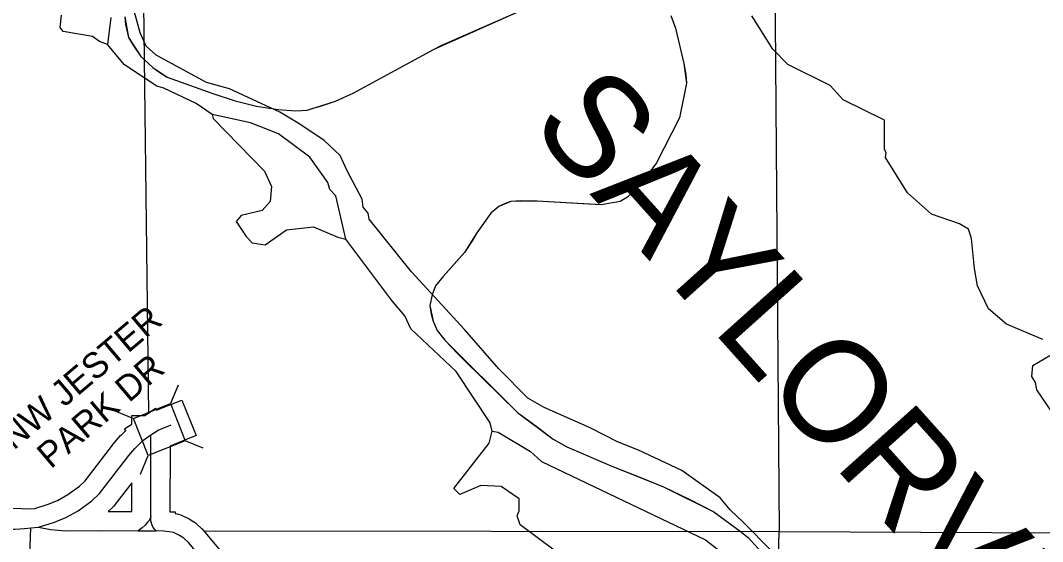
# Model space of a CAD drawing. Extents: x -1403959 to 81668, y -1400582 to 11018.
# Drawn here: x 6398.9 to 6553.7, y 9508.2 to 9587.1 of the extents above; entities that cross this region are included whole.
import ezdxf

# ---------------------------------------------------------------- set-up
doc = ezdxf.new("R2010")
doc.units = 0
for name, color, linetype in [('tdCiCoBndryTxt', 7, 'Continuous'), ('tdCiRROwnerTxt', 7, 'Continuous'), ('tdCiSecText', 7, 'Continuous'), ('tdCiSectLine', 7, 'Continuous'), ('tdCoCityStreetMajor', 7, 'Continuous'), ('tdCoClipBndry', 7, 'Continuous'), ('tdCoSectNmbr', 7, 'Continuous'), ('tdCoSurfBitum', 7, 'Continuous'), ('tdCoSurfConc', 7, 'Continuous'), ('tdCoTwpNameTxt', 7, 'Continuous')]:
    doc.layers.add(name, color=color, linetype=linetype)

msp = doc.modelspace()

# ---------------------------------------------------------------- linework, layer by layer
at = {"layer": 'tdCiCoBndryTxt'}
for points in [[(6418.65, 9524.35), (6419.75, 9525.04), (6421.71, 9525.83)], [(6401.63, 9510.33), (6404.04, 9511.09), (6405.77, 9511.8), (6407.6, 9512.84), (6409.68, 9514.34), (6410.83, 9515.43), (6415.27, 9521.22), (6416.21, 9522.26), (6417.44, 9523.49), (6418.65, 9524.35)], [(6419.42, 9509.79), (6419.19, 9510.04), (6418.99, 9510.32), (6418.83, 9510.63), (6418.72, 9510.95), (6418.65, 9511.29), (6418.63, 9511.63), (6418.63, 9511.95), (6418.65, 9524.35)], [(6418.63, 9511.95), (6418.44, 9511.42), (6418.14, 9511.08), (6417.77, 9510.63), (6417.32, 9510.23), (6416.72, 9509.8)], [(6370, 9510), (6387.18, 9510.05), (6398.08, 9510.05), (6399.48, 9510.15), (6400.45, 9510.23), (6401.63, 9510.33)], [(6401.63, 9510.33), (6403.41, 9510), (6405.77, 9509.79), (6410.89, 9509.82), (6416.72, 9509.8), (6418.29, 9509.79), (6419.42, 9509.79)], [(6441.88, 9466.82), (6441.56, 9467.69), (6441.46, 9468.69), (6441.48, 9470.01), (6441.61, 9473.37), (6441.7, 9476.58), (6441.36, 9478.55), (6439.76, 9483.71), (6437.47, 9491.1), (6436.67, 9492.76), (6435.76, 9494.12), (6434.5, 9495.86), (6424.33, 9508.02), (6423.62, 9508.68), (6422.96, 9509.1), (6422.04, 9509.52), (6421.39, 9509.64), (6420.54, 9509.76), (6419.42, 9509.79)]]:
    msp.add_lwpolyline(points, dxfattribs=at)
at = {"layer": 'tdCiRROwnerTxt'}
msp.add_lwpolyline([(6405.79, 9491.03), (6404.68, 9492.17), (6403.18, 9493.73), (6401.54, 9496.26), (6400.73, 9498.55), (6400.29, 9500.37), (6400.14, 9502.07), (6400.45, 9510.23)], dxfattribs=at)
at = {"layer": 'tdCiSecText'}
for points in [[(6422.77, 9531.84), (6421.59, 9529.06), (6423.85, 9523.45)], [(6413.19, 9527.98), (6415.98, 9526.8), (6421.59, 9529.06)], [(6417.05, 9518.4), (6418.24, 9521.18), (6415.98, 9526.8)], [(6426.57, 9522.29), (6423.85, 9523.45), (6418.24, 9521.18)]]:
    msp.add_lwpolyline(points, dxfattribs=at)
at = {"layer": 'tdCiSectLine'}
for points in [[(6397.66, 9513.24), (6400.38, 9513.14), (6401.07, 9513.19), (6403.05, 9513.82), (6404.49, 9514.41), (6406.03, 9515.29), (6407.82, 9516.58), (6408.67, 9517.38), (6412.97, 9522.99), (6413.09, 9523.14), (6413.12, 9523.17), (6414.05, 9524.21), (6414.16, 9524.32), (6414.16, 9524.32), (6414.82, 9524.98), (6414.64, 9525.25), (6415.75, 9525.95), (6415.75, 9527.25), (6417.72, 9527.25), (6419.34, 9528.39), (6419.55, 9528.09), (6420.62, 9528.52), (6423.31, 9529.61), (6425.48, 9524.22), (6422.79, 9523.14), (6421.55, 9522.64), (6421.53, 9512.69), (6422.33, 9512.68), (6422.33, 9512.42), (6422.6, 9512.36), (6422.6, 9512.36), (6422.79, 9512.32), (6422.97, 9512.26), (6423.15, 9512.2), (6423.22, 9512.16), (6424.14, 9511.75), (6424.24, 9511.71), (6424.41, 9511.62), (6424.53, 9511.54), (6425.19, 9511.12), (6425.23, 9511.09), (6425.38, 9510.98), (6425.53, 9510.86), (6425.58, 9510.81), (6426.3, 9510.15), (6426.39, 9510.07), (6426.52, 9509.93), (6426.56, 9509.88), (6436.72, 9497.72)], [(6415.73, 9512.7), (6415.73, 9517.06), (6413.13, 9513.67), (6413.01, 9513.52), (6412.88, 9513.38), (6412.83, 9513.33), (6412.18, 9512.72), (6415.73, 9512.7)]]:
    msp.add_lwpolyline(points, dxfattribs=at)
at = {"layer": 'tdCoCityStreetMajor'}
for points in [[(6417.33, 9606.13), (6418.27, 9527.53)], [(6513.07, 9606.38), (6513.8, 9509.68)], [(6426.6, 9509.78), (6513.8, 9509.68)], [(6511.21, 9405.21), (6513.8, 9509.68)], [(6513.8, 9509.68), (6610.4, 9509.24)]]:
    msp.add_lwpolyline(points, dxfattribs=at)
at = {"layer": 'tdCoClipBndry'}
for points in [[(6414.69, 9587.68), (6415.25, 9584.52), (6417.1, 9581.64), (6418.95, 9579.98), (6421.1, 9578.53), (6428.04, 9576.03), (6431.39, 9574.94), (6434.65, 9574.11), (6437.9, 9573.61), (6440.57, 9573.4), (6442.29, 9573.54), (6446.62, 9574.86), (6449.29, 9576.09), (6461.53, 9582.78), (6474.48, 9588.52)], [(6497.42, 9587.87), (6498.1, 9585.96), (6499.38, 9580.59), (6499.76, 9577.62), (6498.74, 9572.35), (6495.25, 9565.52), (6492.78, 9562.16), (6490.86, 9560.34), (6489.72, 9559.69), (6486.86, 9559.16), (6477.13, 9559.75), (6473.15, 9559.66), (6471.35, 9558.91), (6470.13, 9557.89), (6467.99, 9554.94), (6466.14, 9551.94), (6462.9, 9548.34), (6461.75, 9546.91), (6461.23, 9545.56), (6460.89, 9543.91), (6461.42, 9541.56), (6462.03, 9540.16), (6463.16, 9538.69), (6474.2, 9527.71), (6479.59, 9523.68), (6481.67, 9522.52), (6488.45, 9519.58), (6496.3, 9516.44), (6503.92, 9512.68), (6508.11, 9509.57), (6509.16, 9508.71), (6514.03, 9503.4)]]:
    msp.add_lwpolyline(points, dxfattribs=at)
at = {"layer": 'tdCoSurfBitum'}
for points in [[(6512.78, 9506.67), (6508.36, 9511.11), (6506.38, 9512.95), (6504.86, 9514.79), (6499.07, 9518.94), (6492.52, 9522.02), (6489.32, 9523.25), (6485.2, 9525.4), (6478.19, 9528.49), (6475.75, 9529.87), (6471.33, 9534.32), (6466.16, 9540.29), (6458.1, 9549.03), (6451.71, 9556.99), (6451.56, 9557.91), (6450.8, 9558.83), (6450.65, 9560.05), (6448.38, 9564.33), (6447.31, 9566.63), (6444.88, 9568.93), (6441.22, 9571.38), (6438.17, 9573.23), (6430.55, 9576.77), (6427.04, 9577.7), (6419.42, 9581.85), (6417.9, 9583.23), (6416.99, 9585.22), (6415.78, 9589.66)], [(6412.55, 9587.56), (6412.08, 9583.44), (6410.86, 9583.9), (6409.79, 9584.67), (6405.37, 9585.45), (6404.91, 9586.06), (6405.07, 9587.89)], [(6553.76, 9538.8), (6548.27, 9541.1), (6545.52, 9543.4), (6543.85, 9546.91), (6543.4, 9549.51), (6542.95, 9554.09), (6542.49, 9555.47), (6541.14, 9556.31), (6536.88, 9557.74), (6533.24, 9561), (6529.9, 9566.36), (6530.05, 9567.12), (6529.75, 9567.58), (6529.77, 9572.01), (6523.52, 9575.08), (6521.54, 9577.23), (6515.14, 9580.46), (6512.85, 9582.76), (6509.67, 9587.81)], [(6419.54, 9577.15), (6414.66, 9580.38), (6412.08, 9583.44)], [(6427.92, 9572.85), (6425.48, 9574.54), (6420.61, 9576.84), (6419.54, 9577.15)], [(6448.16, 9553.99), (6446.66, 9560.56), (6445.75, 9561.48), (6445.44, 9562.55), (6442.71, 9566.38), (6437.99, 9569.91), (6433.72, 9571.6), (6427.92, 9572.85)], [(6427.92, 9572.85), (6428.07, 9572.24), (6435.83, 9564.27), (6436.89, 9561.97), (6436.73, 9559.68), (6435.5, 9558.32), (6432.29, 9557.56), (6431.53, 9556.65), (6433.05, 9554.36), (6433.96, 9553.44), (6435.94, 9553.12), (6439.16, 9555.4), (6443.28, 9555.84), (6446.94, 9554.3), (6448.16, 9553.99)], [(6470.35, 9524.91), (6470.05, 9526.13), (6464.89, 9533.93), (6458.04, 9540.37), (6457.13, 9542.36), (6455.15, 9544.66), (6448.16, 9553.99)], [(6555.11, 9527.81), (6552.83, 9531.17), (6552.67, 9532.24), (6552.07, 9533.16), (6552.22, 9534.84), (6554.82, 9536.36)], [(6479.91, 9506.7), (6474.58, 9510.69), (6474.13, 9512.07), (6474.43, 9512.83), (6474.44, 9514.66), (6471.7, 9516.5), (6468.64, 9516.67), (6465.43, 9515.31), (6464.52, 9516.23), (6469.89, 9523.08), (6470.35, 9524.91), (6471.27, 9524.75), (6476.14, 9521.83), (6477.82, 9520.3), (6502.68, 9508.42), (6506.64, 9505.35)]]:
    msp.add_lwpolyline(points, dxfattribs=at)
at = {"layer": 'tdCoTwpNameTxt'}
for points in [[(6414.69, 9587.68), (6414.79, 9586.47), (6415.25, 9584.52), (6415.83, 9583.52), (6417.1, 9581.64), (6418.95, 9579.98), (6419.97, 9579.2), (6421.1, 9578.53), (6428.04, 9576.03), (6431.39, 9574.94), (6434.65, 9574.11), (6436.58, 9573.8), (6437.9, 9573.61), (6440.57, 9573.4), (6442.29, 9573.54), (6443.21, 9573.82), (6444.34, 9574.11), (6446.62, 9574.86), (6449.29, 9576.09), (6461.53, 9582.78), (6462.63, 9583.32), (6474.48, 9588.52)], [(6497.42, 9587.87), (6498.1, 9585.96), (6499.38, 9580.59), (6499.66, 9578.91), (6499.76, 9577.62), (6498.74, 9572.35)], [(6498.74, 9572.35), (6495.25, 9565.52), (6492.78, 9562.16), (6490.86, 9560.34), (6489.72, 9559.69), (6486.86, 9559.16), (6484.05, 9559.33), (6477.13, 9559.75), (6474.65, 9559.76), (6473.15, 9559.66), (6472.3, 9559.38), (6471.35, 9558.91), (6470.13, 9557.89), (6467.99, 9554.94), (6467.32, 9553.73), (6466.14, 9551.94), (6463.82, 9549.32), (6462.9, 9548.34), (6461.75, 9546.91), (6461.23, 9545.56), (6460.89, 9543.91), (6461.1, 9542.63), (6461.42, 9541.56), (6462.03, 9540.16), (6463.16, 9538.69), (6465.16, 9536.62), (6466.14, 9535.62), (6474.2, 9527.71), (6476.97, 9525.71), (6479.59, 9523.68), (6481.67, 9522.52), (6488.45, 9519.58), (6492.47, 9518.01), (6496.3, 9516.44), (6500.2, 9514.58), (6503.92, 9512.68), (6508.11, 9509.57), (6509.16, 9508.71), (6514.03, 9503.4)]]:
    msp.add_lwpolyline(points, dxfattribs=at)

# ---------------------------------------------------------------- texts
at = {"layer": 'tdCoSectNmbr'}
for s, p in [('NW JESTER', (6397.86, 9521.92)), ('PARK DR', (6403.47, 9519.07))]:
    msp.add_text(s, height=3.869, rotation=40.3149, dxfattribs=at).set_placement(p)
at = {"layer": 'tdCoSurfConc'}
msp.add_text('SAYLORVILLE', height=15.4765, rotation=311.9085, dxfattribs=at).set_placement((6475.82, 9571.11))

doc.saveas('drawing.dxf')
